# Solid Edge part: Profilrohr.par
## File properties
Username: bmolnar
Dokumentum tartalom típus: 0
Author: bmolnar
Last saved by: bmolnar
Revision: 77
Sűrűség: 0,000 kg/m^3
Pontosság: 0,990
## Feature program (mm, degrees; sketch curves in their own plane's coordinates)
base feature "unnamed BaseFeature 1"
thread "unnamed Thread 1"
thread "Menet_2"  ThreadDepth = 6 mm
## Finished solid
Body 1: solid body, 153 faces, 364 edges, 252 vertices.
  Faces by surface: plane 74, cylinder 65, cone 10, torus 4
  Edges by curve: line 220, circle 140, curve on surface 2, spline 2
Bounding box of the edges (mm; curved faces can reach further): 46.000 x 51.000 x 44.500, from (-23, -24, 0) to (23, 27, 44.5).
Cylindrical faces by radius (mm): R0.3 x24, R0.8 x2, R2.9 x8, R4.283 x4, R4.4 x16, R16 x1, R16.85 x2, R17.05 x2, R17.9 x2, R30 x4
Conical faces (half-angle, radius in mm at the cone's reference point): 21 deg R16.325 x2, 45 deg R4.783 x2, 45 deg R17.1 x2, 45 deg R17.15 x2, 45 deg R17.2 x2
Toroidal faces (ring radius, tube radius in mm): R17.7 r0.2 x4
Planar faces by outward normal: +x 6, +y 9, +z 8, -x 6, -y 5, -z 8, oblique 32
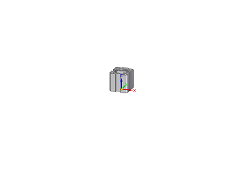
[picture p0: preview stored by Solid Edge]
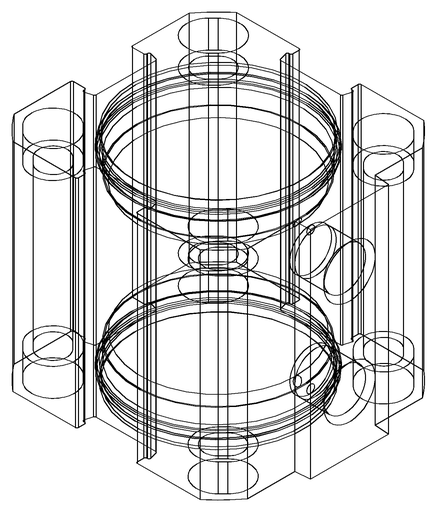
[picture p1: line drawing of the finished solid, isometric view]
